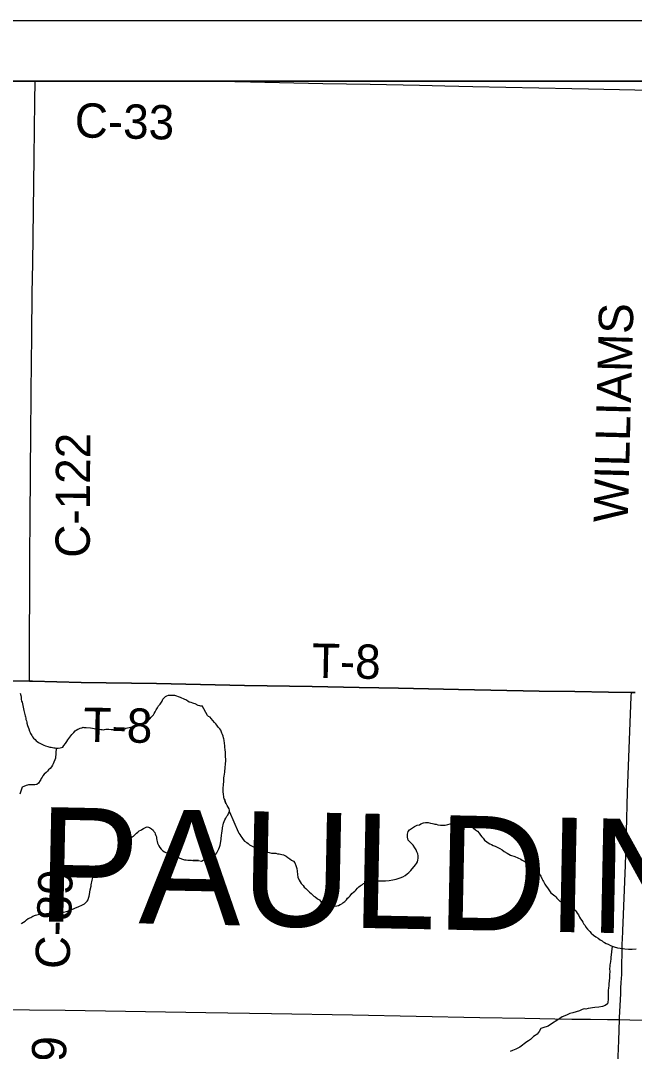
# Model space of a CAD drawing. Extents: x 0 to 64.8, y -5 to 22.
# Drawn here: x 2.737 to 3.754, y 19.293 to 21 of the extents above; entities that cross this region are included whole.
import ezdxf

# ---------------------------------------------------------------- set-up
doc = ezdxf.new("R2010")
doc.units = 0
for name, color, linetype in [('GM_X_Adjacent_County', 7, 'Continuous'), ('GM_X_Adjacent_County_Text', 7, 'Continuous'), ('GM_X_County', 7, 'Continuous'), ('GM_X_County_Road', 7, 'Continuous'), ('GM_X_County_Road_Text', 7, 'Continuous'), ('GM_X_Minor_River', 7, 'Continuous'), ('GM_X_Township', 7, 'Continuous'), ('GM_X_Township_Road', 7, 'Continuous'), ('GM_X_Township_Road_Text', 7, 'Continuous'), ('SH_Data', 7, 'Continuous')]:
    doc.layers.add(name, color=color, linetype=linetype)

msp = doc.modelspace()

# ---------------------------------------------------------------- linework, layer by layer
at = {"layer": 'GM_X_Adjacent_County'}
for points in [[(8.9, 19.781), (8.9, 20.9), (2.1, 20.9), (2.1, 19.9176)], [(2.1, 19.9176), (2.1319, 19.9171), (2.2376, 19.9153), (2.3371, 19.9137), (2.4366, 19.912), (2.6014, 19.909), (2.7133, 19.9067), (2.7182, 19.9066), (2.7516, 19.9061), (2.7568, 19.906), (2.8377, 19.9042), (2.962, 19.9024), (3.1081, 19.8993), (3.22, 19.8972), (3.2978, 19.8956), (3.3631, 19.8945), (3.4625, 19.8926), (3.5962, 19.8899), (3.6553, 19.8889), (3.7112, 19.8882), (3.749, 19.8876), (3.7551, 19.8875)], [(3.7551, 19.8875), (3.749, 19.8876), (3.7112, 19.8882), (3.6553, 19.8889), (3.5962, 19.8899), (3.4625, 19.8926), (3.3631, 19.8945), (3.2978, 19.8956), (3.22, 19.8972), (3.1081, 19.8993), (2.962, 19.9024), (2.8377, 19.9042), (2.7568, 19.906), (2.7516, 19.9061), (2.7182, 19.9066), (2.7133, 19.9067), (2.6014, 19.909), (2.4366, 19.912), (2.3371, 19.9137), (2.2376, 19.9153), (2.1319, 19.9171), (2.1, 19.9176)]]:
    msp.add_lwpolyline(points, dxfattribs=at)
at = {"layer": 'GM_X_County'}
for points in [[(8.9, 19.781), (8.9, 20.9), (2.1, 20.9), (2.1, 19.9176)], [(3.7551, 19.8875), (3.749, 19.8876), (3.7112, 19.8882), (3.6553, 19.8889), (3.5962, 19.8899), (3.4625, 19.8926), (3.3631, 19.8945), (3.2978, 19.8956), (3.22, 19.8972), (3.1081, 19.8993), (2.962, 19.9024), (2.8377, 19.9042), (2.7568, 19.906), (2.7516, 19.9061), (2.7182, 19.9066), (2.7133, 19.9067), (2.6014, 19.909), (2.4366, 19.912), (2.3371, 19.9137), (2.2376, 19.9153), (2.1319, 19.9171), (2.1, 19.9176)], [(2.1, 19.9176), (2.1319, 19.9171), (2.2376, 19.9153), (2.3371, 19.9137), (2.4366, 19.912), (2.6014, 19.909), (2.7133, 19.9067), (2.7182, 19.9066), (2.7516, 19.9061), (2.7568, 19.906), (2.8377, 19.9042), (2.962, 19.9024), (3.1081, 19.8993), (3.22, 19.8972), (3.2978, 19.8956), (3.3631, 19.8945), (3.4625, 19.8926), (3.5962, 19.8899), (3.6553, 19.8889), (3.7112, 19.8882), (3.749, 19.8876), (3.7551, 19.8875)]]:
    msp.add_lwpolyline(points, dxfattribs=at)
at = {"layer": 'GM_X_County_Road'}
for points in [[(2.7516, 19.9061), (2.7517, 19.927), (2.752, 19.9544), (2.7524, 20.0793), (2.7525, 20.1197), (2.753, 20.1695), (2.7531, 20.19), (2.7533, 20.2347), (2.7534, 20.2608), (2.7538, 20.3087), (2.7544, 20.3858), (2.7558, 20.4784), (2.7565, 20.5486), (2.7573, 20.5983), (2.7597, 20.7736), (2.7609, 20.8662), (2.7615, 20.9)], [(3.0661, 20.9), (3.1178, 20.8989), (3.2377, 20.8961), (3.316, 20.8946), (3.3981, 20.8929), (3.4397, 20.8919), (3.4864, 20.8911), (3.6504, 20.8875), (3.6778, 20.8868), (3.7549, 20.8855), (3.7833, 20.885)], [(2.7157, 19.3627), (2.7519, 19.3619), (2.811, 19.3615), (3.0442, 19.3578), (3.153, 19.3559), (3.2867, 19.3538), (3.4981, 19.3496), (3.5727, 19.3481), (3.6224, 19.3473), (3.6504, 19.3468), (3.6815, 19.3465), (3.7094, 19.3463), (3.7292, 19.3458)], [(3.7292, 19.3458), (3.7467, 19.3453), (3.7871, 19.3441), (3.8399, 19.3421), (3.8989, 19.3396), (3.9331, 19.3381), (3.961, 19.3372), (3.9983, 19.336), (4.1226, 19.3323), (4.1848, 19.3308), (4.2083, 19.3299)]]:
    msp.add_lwpolyline(points, dxfattribs=at)
at = {"layer": 'GM_X_Minor_River'}
for points in [[(2.7363, 19.8862), (2.7376, 19.8823), (2.7379, 19.8796), (2.7381, 19.8762), (2.7388, 19.8732), (2.7395, 19.8712), (2.7401, 19.8685), (2.7408, 19.8662), (2.7414, 19.8632), (2.7421, 19.8605), (2.7427, 19.8578), (2.744, 19.8509), (2.7447, 19.849), (2.745, 19.8471), (2.7456, 19.8451), (2.7459, 19.8428), (2.7466, 19.8405), (2.7473, 19.8386), (2.7476, 19.8367), (2.7486, 19.8329), (2.7496, 19.8302), (2.7506, 19.8271), (2.7516, 19.8236), (2.7527, 19.8213), (2.7537, 19.8194), (2.7555, 19.8162), (2.757, 19.8139), (2.7584, 19.8119), (2.761, 19.8096), (2.7628, 19.8076), (2.7646, 19.8064), (2.7669, 19.8048), (2.7691, 19.8035), (2.7713, 19.8023), (2.7736, 19.8015), (2.7754, 19.8002), (2.7784, 19.7994), (2.7822, 19.7981), (2.7856, 19.7972), (2.7879, 19.7967), (2.7897, 19.7962), (2.7924, 19.7958), (2.7943, 19.7957), (2.7969, 19.7952), (2.7996, 19.7955), (2.8027, 19.7957), (2.805, 19.7964), (2.8069, 19.7967), (2.8089, 19.7996), (2.8113, 19.8033), (2.8137, 19.8063), (2.8154, 19.8093), (2.8222, 19.8177), (2.8254, 19.8214), (2.8274, 19.824), (2.8293, 19.825), (2.8317, 19.8265), (2.8336, 19.8275), (2.8356, 19.8282), (2.8383, 19.8292), (2.8402, 19.8299), (2.8421, 19.8298), (2.8455, 19.8297), (2.8527, 19.829), (2.8561, 19.8285), (2.8588, 19.828), (2.8626, 19.8275), (2.8652, 19.8274), (2.8671, 19.8265), (2.8701, 19.826), (2.872, 19.826), (2.8743, 19.8259), (2.8762, 19.8262), (2.8785, 19.8265), (2.8808, 19.8268), (2.8835, 19.8266), (2.8872, 19.8261), (2.8907, 19.826), (2.8956, 19.8258), (2.9029, 19.8262), (2.9071, 19.8268), (2.9098, 19.8275), (2.9117, 19.8282), (2.9144, 19.8288), (2.9171, 19.8295), (2.9194, 19.8301), (2.9217, 19.8308), (2.9236, 19.8315), (2.9267, 19.8321), (2.9298, 19.8335), (2.9394, 19.8365), (2.9414, 19.8372), (2.9448, 19.8386), (2.9468, 19.8397), (2.9491, 19.8415), (2.9511, 19.8437), (2.9535, 19.8466)], [(2.9535, 19.8466), (2.9571, 19.8506), (2.9583, 19.8525), (2.96, 19.8555), (2.9616, 19.8588), (2.9637, 19.8622), (2.9657, 19.8655), (2.9681, 19.8684), (2.9705, 19.8714), (2.9714, 19.8732), (2.9726, 19.8762), (2.975, 19.8788), (2.9774, 19.8806), (2.9793, 19.882), (2.982, 19.8831), (2.9847, 19.8833), (2.9866, 19.8833), (2.9904, 19.8831), (2.9923, 19.883), (2.9953, 19.8822), (2.9979, 19.8809), (3.0013, 19.8796), (3.0039, 19.8788), (3.0062, 19.8775), (3.0088, 19.8767), (3.0107, 19.8758), (3.014, 19.8738), (3.0162, 19.8722), (3.0192, 19.8713), (3.0219, 19.8704), (3.0237, 19.87), (3.026, 19.8691), (3.0308, 19.8667), (3.0335, 19.8658), (3.035, 19.8653), (3.0378, 19.8652)], [(3.0744, 19.7109), (3.0727, 19.7229), (3.0729, 19.7282), (3.0731, 19.7355), (3.0736, 19.7396), (3.0737, 19.743), (3.0738, 19.7461), (3.0743, 19.7491), (3.0747, 19.7525), (3.0752, 19.7555), (3.0753, 19.7582), (3.0758, 19.7612), (3.0758, 19.7643), (3.0763, 19.7677), (3.0768, 19.7703), (3.0769, 19.7734), (3.0769, 19.776), (3.077, 19.7779), (3.0767, 19.7802), (3.0765, 19.7855), (3.0765, 19.7882), (3.0759, 19.7932), (3.0756, 19.7966), (3.0754, 19.8), (3.0751, 19.8027), (3.0747, 19.8046), (3.0744, 19.8069), (3.0741, 19.8088), (3.0738, 19.8107), (3.0731, 19.8126), (3.0728, 19.8153), (3.0717, 19.818), (3.0706, 19.8199), (3.0699, 19.8218), (3.0689, 19.8249), (3.0674, 19.8272), (3.0644, 19.83), (3.0623, 19.8335), (3.0608, 19.8354), (3.0586, 19.8378), (3.0557, 19.8413), (3.0527, 19.8444), (3.0509, 19.8467), (3.0486, 19.8479), (3.0468, 19.8495), (3.0378, 19.8652)], [(2.7958, 19.7951), (2.7951, 19.7789), (2.791, 19.7696), (2.7897, 19.767), (2.7881, 19.7644), (2.7861, 19.7618), (2.7833, 19.7593), (2.7817, 19.757), (2.7793, 19.7552), (2.7762, 19.752), (2.7738, 19.7494), (2.7726, 19.7475), (2.7713, 19.7453), (2.7705, 19.7434), (2.7693, 19.7416), (2.7665, 19.7375), (2.7641, 19.7353), (2.7606, 19.7347), (2.7568, 19.7345), (2.7526, 19.7347), (2.7503, 19.7344), (2.7484, 19.7341), (2.7461, 19.7334), (2.7426, 19.732), (2.7395, 19.7306), (2.7356, 19.719)], [(3.0319, 19.6094), (3.037, 19.6083), (3.0424, 19.6116), (3.0478, 19.613), (3.0516, 19.6141), (3.0543, 19.6148), (3.0566, 19.6151), (3.0581, 19.6174), (3.0605, 19.6196), (3.0624, 19.6218), (3.064, 19.6252), (3.0656, 19.6286), (3.0668, 19.6312), (3.0676, 19.6346), (3.0685, 19.6376), (3.0689, 19.6414), (3.0694, 19.6441), (3.0694, 19.6467), (3.0699, 19.6498), (3.0699, 19.6517), (3.0707, 19.6539), (3.0708, 19.6589), (3.0717, 19.6615), (3.0717, 19.6634), (3.0721, 19.6661), (3.0726, 19.6683), (3.073, 19.671), (3.0754, 19.6766), (3.077, 19.6796), (3.079, 19.6826), (3.0802, 19.6845), (3.0817, 19.6871), (3.0833, 19.6901), (3.083, 19.6924), (3.0827, 19.6947), (3.0812, 19.6974), (3.0794, 19.7005), (3.0779, 19.7035), (3.0768, 19.7055), (3.0748, 19.7108), (3.0768, 19.7055)], [(3.0833, 19.6901), (3.0978, 19.6567), (3.0989, 19.6548), (3.1004, 19.6521), (3.1018, 19.6494), (3.1037, 19.6475), (3.1059, 19.644), (3.1081, 19.6413), (3.1118, 19.6393), (3.1141, 19.6374), (3.1163, 19.6354), (3.1197, 19.6335), (3.1231, 19.6319), (3.1378, 19.6251), (3.1438, 19.623), (3.1487, 19.6225), (3.1529, 19.6217), (3.1575, 19.6216), (3.1601, 19.6212), (3.1628, 19.6203), (3.1654, 19.6203), (3.1677, 19.6198), (3.17, 19.6194), (3.1726, 19.6186), (3.1749, 19.6178), (3.1771, 19.6166), (3.1801, 19.6142), (3.1831, 19.6123), (3.1861, 19.6099), (3.1891, 19.6083), (3.1917, 19.6052), (3.1931, 19.601), (3.1938, 19.5991), (3.1945, 19.5961), (3.1952, 19.5915), (3.1958, 19.5862), (3.1965, 19.5816), (3.1987, 19.577), (3.2001, 19.5739), (3.202, 19.5712), (3.2034, 19.5693), (3.2053, 19.5677), (3.2068, 19.5654), (3.2097, 19.5627), (3.2127, 19.5596), (3.2157, 19.5568), (3.2183, 19.5545), (3.2205, 19.5522), (3.2228, 19.5502), (3.225, 19.549), (3.2284, 19.5463), (3.2303, 19.5451), (3.2325, 19.5439), (3.2351, 19.5404), (3.237, 19.5389), (3.2407, 19.5365), (3.2437, 19.5357), (3.246, 19.5353), (3.249, 19.5344), (3.2528, 19.534), (3.2555, 19.5335), (3.2574, 19.5339), (3.2608, 19.5342), (3.2639, 19.5349), (3.2666, 19.5363), (3.2693, 19.5378), (3.2712, 19.5393), (3.2743, 19.5415), (3.277, 19.5444), (3.2786, 19.5467), (3.2809, 19.5485), (3.2829, 19.5508), (3.286, 19.5545), (3.2887, 19.5567), (3.2906, 19.5586), (3.2926, 19.5604), (3.2953, 19.5634), (3.2973, 19.5656), (3.2996, 19.5675), (3.3015, 19.5686), (3.3034, 19.5697), (3.3054, 19.5712), (3.3077, 19.5723), (3.3103, 19.5726), (3.3126, 19.5729), (3.3153, 19.574), (3.3191, 19.5747), (3.3245, 19.5749), (3.3298, 19.5756), (3.3359, 19.5758), (3.3416, 19.5757), (3.3477, 19.5763), (3.3538, 19.5773), (3.3595, 19.5783), (3.366, 19.5804), (3.3706, 19.5822), (3.3745, 19.5844), (3.3776, 19.587), (3.3803, 19.5896)], [(2.7386, 19.5046), (2.7394, 19.5057), (2.7417, 19.5072), (2.7444, 19.509), (2.7468, 19.5109), (2.7499, 19.5131), (2.7541, 19.5149), (2.7576, 19.5171), (2.7618, 19.5189), (2.766, 19.52), (2.7702, 19.5206), (2.774, 19.5209), (2.7767, 19.5212), (2.7802, 19.5215), (2.7847, 19.5218), (2.7905, 19.5224), (2.7966, 19.5231), (2.8031, 19.5237), (2.8084, 19.5239), (2.813, 19.5246), (2.8165, 19.5257), (2.8211, 19.5274), (2.8272, 19.5304), (2.8334, 19.5329), (2.8384, 19.5354), (2.843, 19.5376), (2.8454, 19.5398), (2.8473, 19.5417), (2.8489, 19.5443), (2.8497, 19.5469), (2.8505, 19.55), (2.8514, 19.553), (2.8518, 19.5568), (2.8523, 19.5606), (2.854, 19.567), (2.854, 19.5689), (2.8545, 19.5716), (2.8549, 19.5738), (2.8557, 19.5765), (2.8562, 19.5791), (2.857, 19.5814), (2.8578, 19.5833), (2.8586, 19.5855), (2.8602, 19.5882), (2.8625, 19.5911), (2.8641, 19.5934), (2.866, 19.5945), (2.868, 19.596), (2.8703, 19.5974), (2.873, 19.5989), (2.8765, 19.6007), (2.8799, 19.6022), (2.8842, 19.6051), (2.8896, 19.6076), (2.893, 19.6091), (2.8957, 19.6109), (2.8985, 19.6135), (2.902, 19.6169), (2.9051, 19.621), (2.9083, 19.6251), (2.9107, 19.6296), (2.9138, 19.6348), (2.9162, 19.6386), (2.9178, 19.6408), (2.919, 19.6438), (2.9202, 19.6457), (2.9221, 19.6483), (2.9241, 19.6498), (2.9272, 19.6528), (2.9291, 19.6543), (2.9311, 19.6561), (2.9338, 19.6583), (2.9361, 19.6598), (2.938, 19.6609), (2.9407, 19.6624), (2.945, 19.6645), (2.9469, 19.6653), (2.9488, 19.6645), (2.9507, 19.6637), (2.9537, 19.6617), (2.9567, 19.6593), (2.9578, 19.6574), (2.9593, 19.6555), (2.9603, 19.6532), (2.9614, 19.6509), (2.9621, 19.6486), (2.9625, 19.6459), (2.9628, 19.6432), (2.9631, 19.6406), (2.9638, 19.6379), (2.9649, 19.6356), (2.966, 19.6336), (2.9678, 19.6309), (2.9701, 19.6282), (2.9727, 19.6255), (2.9757, 19.6239), (2.9779, 19.6227), (2.9802, 19.6219), (2.9829, 19.6211), (2.9859, 19.6199), (2.9893, 19.6183)], [(3.3803, 19.5896), (3.3834, 19.593), (3.3916, 19.6023), (3.3932, 19.6045), (3.3944, 19.6072), (3.3952, 19.6098), (3.3957, 19.6132), (3.3958, 19.617), (3.3951, 19.6201), (3.3936, 19.6235), (3.3922, 19.627), (3.39, 19.6304), (3.3874, 19.6347), (3.3837, 19.6386), (3.3807, 19.6413), (3.3792, 19.6432), (3.3782, 19.6482), (3.3783, 19.6527), (3.3784, 19.655), (3.3792, 19.6573), (3.3815, 19.6599), (3.3846, 19.6625), (3.3896, 19.6654), (3.3942, 19.6676), (3.3981, 19.6686), (3.4004, 19.6701), (3.4046, 19.6715), (3.408, 19.6722), (3.4122, 19.6721), (3.416, 19.6713), (3.4194, 19.6704), (3.4217, 19.67), (3.4236, 19.6696), (3.4254, 19.6695), (3.4281, 19.6683), (3.4326, 19.6678), (3.4364, 19.6678), (3.4406, 19.668), (3.4448, 19.6687), (3.449, 19.6698), (3.454, 19.6708), (3.459, 19.6722), (3.4639, 19.6728), (3.4674, 19.6731), (3.47, 19.6731), (3.473, 19.6715), (3.4835, 19.6652), (3.4873, 19.6628), (3.491, 19.6601), (3.494, 19.6577), (3.497, 19.6546), (3.4992, 19.6515), (3.5014, 19.6484), (3.5036, 19.6461), (3.5058, 19.643), (3.5096, 19.6403), (3.5118, 19.6387), (3.5145, 19.6371), (3.5171, 19.6359), (3.5201, 19.6344), (3.5235, 19.6328), (3.5269, 19.6312), (3.531, 19.6292), (3.5348, 19.6268), (3.5385, 19.6244), (3.543, 19.6217), (3.5486, 19.6181), (3.5558, 19.6157), (3.5607, 19.6137), (3.5656, 19.6117), (3.5682, 19.6101), (3.5731, 19.6073), (3.5753, 19.6058), (3.5809, 19.6011), (3.5843, 19.5995), (3.5881, 19.596), (3.5925, 19.5917), (3.5962, 19.5871), (3.5992, 19.5832), (3.6006, 19.5797), (3.6021, 19.5763), (3.6035, 19.5744), (3.6046, 19.5724), (3.6057, 19.5701), (3.6076, 19.567), (3.6102, 19.5643), (3.6124, 19.5605), (3.6157, 19.5555), (3.6198, 19.5527), (3.622, 19.5508), (3.6239, 19.5492), (3.6254, 19.5469), (3.6276, 19.5446), (3.6302, 19.5422), (3.6385, 19.5379), (3.6415, 19.5363), (3.6445, 19.5347), (3.6486, 19.5319), (3.6516, 19.53), (3.6538, 19.5284), (3.6557, 19.5268)], [(2.9893, 19.6183), (2.9927, 19.6163), (2.9976, 19.6147), (3.001, 19.6131), (3.0051, 19.6115), (3.0089, 19.6106), (3.0116, 19.6102), (3.0139, 19.6097), (3.0158, 19.6097), (3.018, 19.6096), (3.0203, 19.6096), (3.0222, 19.6092), (3.0319, 19.6094), (3.0222, 19.6092)], [(3.6557, 19.5268), (3.6576, 19.5249), (3.6594, 19.5222), (3.6612, 19.5191), (3.6631, 19.5156), (3.6649, 19.5126), (3.6667, 19.5099), (3.6686, 19.5072), (3.67, 19.5041), (3.6722, 19.5014), (3.6737, 19.4991), (3.6763, 19.4956), (3.68, 19.4917), (3.6826, 19.489), (3.686, 19.4859), (3.6901, 19.4831), (3.6938, 19.4808), (3.6972, 19.478), (3.7006, 19.4761), (3.7024, 19.4749), (3.7047, 19.4733), (3.7073, 19.4717), (3.7107, 19.4705), (3.7145, 19.4685), (3.7205, 19.4661), (3.7262, 19.4648), (3.7303, 19.464), (3.7334, 19.4635), (3.7353, 19.4635), (3.7383, 19.463), (3.7444, 19.4625), (3.7505, 19.4624), (3.7569, 19.463)], [(3.7172, 19.4674), (3.7152, 19.4487), (3.7147, 19.4465), (3.7143, 19.4419), (3.7138, 19.4385), (3.7134, 19.4363), (3.7133, 19.4336), (3.7128, 19.4302), (3.7131, 19.4252), (3.7126, 19.4203), (3.7125, 19.4154), (3.7124, 19.4097), (3.7119, 19.4059), (3.7115, 19.4021), (3.711, 19.3979), (3.7105, 19.3945), (3.7107, 19.385), (3.7106, 19.382), (3.7105, 19.3778), (3.7101, 19.3759), (3.7101, 19.374), (3.7096, 19.3721), (3.7054, 19.3692), (3.7012, 19.3678), (3.6951, 19.3664), (3.6886, 19.3658), (3.6775, 19.3645), (3.6737, 19.3634), (3.671, 19.3635), (3.6672, 19.3624), (3.663, 19.3606), (3.6573, 19.3589), (3.6519, 19.3571), (3.6469, 19.3557), (3.6427, 19.3539), (3.6385, 19.3521), (3.6343, 19.3503), (3.6304, 19.3477), (3.6254, 19.3444), (3.6184, 19.34), (3.6111, 19.3352), (3.6023, 19.332), (3.5992, 19.3313), (3.5964, 19.326), (3.5929, 19.3216), (3.5898, 19.3197), (3.5868, 19.3179), (3.5821, 19.3131), (3.5786, 19.3105), (3.5759, 19.309), (3.5643, 19.3002), (3.5574, 19.2969), (3.552, 19.2947), (3.5482, 19.2929)]]:
    msp.add_lwpolyline(points, dxfattribs=at)
at = {"layer": 'GM_X_Township'}
for points in [[(5.7946, 20.9), (2.1, 20.9), (2.1, 19.9176)], [(3.7551, 19.8875), (3.749, 19.8876), (3.7112, 19.8882), (3.6553, 19.8889), (3.5962, 19.8899), (3.4625, 19.8926), (3.3631, 19.8945), (3.2978, 19.8956), (3.22, 19.8972), (3.1081, 19.8993), (2.962, 19.9024), (2.8377, 19.9042), (2.7568, 19.906), (2.7516, 19.9061), (2.7182, 19.9066), (2.7133, 19.9067), (2.6014, 19.909), (2.4366, 19.912), (2.3371, 19.9137), (2.2376, 19.9153), (2.1319, 19.9171), (2.1, 19.9176)], [(2.1, 19.9176), (2.1319, 19.9171), (2.2376, 19.9153), (2.3371, 19.9137), (2.4366, 19.912), (2.6014, 19.909), (2.7133, 19.9067), (2.7182, 19.9066), (2.7516, 19.9061), (2.7568, 19.906), (2.8377, 19.9042), (2.962, 19.9024), (3.1081, 19.8993), (3.22, 19.8972), (3.2978, 19.8956), (3.3631, 19.8945), (3.4625, 19.8926), (3.5962, 19.8899), (3.6553, 19.8889), (3.7112, 19.8882), (3.749, 19.8876), (3.7551, 19.8875)]]:
    msp.add_lwpolyline(points, dxfattribs=at)
at = {"layer": 'GM_X_Township_Road'}
for points in [[(2.7182, 19.9066), (2.7516, 19.9061)], [(2.7182, 19.9066), (2.7516, 19.9061)], [(2.7516, 19.9061), (2.7516, 19.9061), (2.7568, 19.906), (2.8377, 19.9042), (2.962, 19.9024), (3.1081, 19.8993), (3.22, 19.8972), (3.2978, 19.8956), (3.3631, 19.8945), (3.4625, 19.8926), (3.5962, 19.8899), (3.6553, 19.8889), (3.7112, 19.8882), (3.749, 19.8876)], [(2.7516, 19.9061), (2.7568, 19.906), (2.8377, 19.9042), (2.962, 19.9024), (3.1081, 19.8993), (3.22, 19.8972), (3.2978, 19.8956), (3.3631, 19.8945), (3.4625, 19.8926), (3.5962, 19.8899), (3.6553, 19.8889), (3.7112, 19.8882), (3.749, 19.8876)], [(3.7342, 19.4784), (3.7349, 19.4928), (3.7392, 19.6014), (3.741, 19.6573), (3.7427, 19.7225), (3.7487, 19.8808), (3.749, 19.8876)], [(3.749, 19.8876), (3.7551, 19.8875)], [(3.749, 19.8876), (3.7551, 19.8875)], [(3.7321, 19.4071), (3.7332, 19.4205), (3.7334, 19.4359), (3.7338, 19.4571), (3.7338, 19.4621), (3.7337, 19.4717), (3.7342, 19.4784)], [(3.7292, 19.3458), (3.7293, 19.3486), (3.7313, 19.3889), (3.7316, 19.3981), (3.7321, 19.4071)], [(3.7105, 18.8383), (3.7108, 18.8453), (3.7146, 18.9478), (3.7211, 19.128), (3.7259, 19.2585), (3.728, 19.3113), (3.7292, 19.3458)]]:
    msp.add_lwpolyline(points, dxfattribs=at)
at = {"layer": 'SH_Data'}
for p, q in [((2, 21), (9, 21)), ((2.1, 20.9), (8.9, 20.9))]:
    msp.add_line(p, q, dxfattribs=at)

# ---------------------------------------------------------------- texts
at = {"layer": 'GM_X_Adjacent_County_Text'}
msp.add_text('PAULDING COUNTY', height=0.189394, rotation=358.8318, dxfattribs=at).set_placement((2.7633, 19.5087))
at = {"layer": 'GM_X_County_Road_Text'}
for s, rotation, p in [('C-33', 358.6287, (2.8263, 20.8068)), ('C-122', 89.7243, (2.8516, 20.1104)), ('C-89', 87.9459, (2.8179, 19.4288))]:
    msp.add_text(s, height=0.05682, rotation=rotation, dxfattribs=at).set_placement(p)
at = {"layer": 'GM_X_Township_Road_Text'}
for s, rotation, p in [('WILLIAMS', 88.496, (3.743, 20.1685)), ('T-8', 358.8663, (3.2192, 19.912)), ('T-8', 359.0457, (2.8409, 19.8058)), ('T-89', 88.2318, (2.8086, 19.1614))]:
    msp.add_text(s, height=0.05682, rotation=rotation, dxfattribs=at).set_placement(p)

doc.saveas('drawing.dxf')
